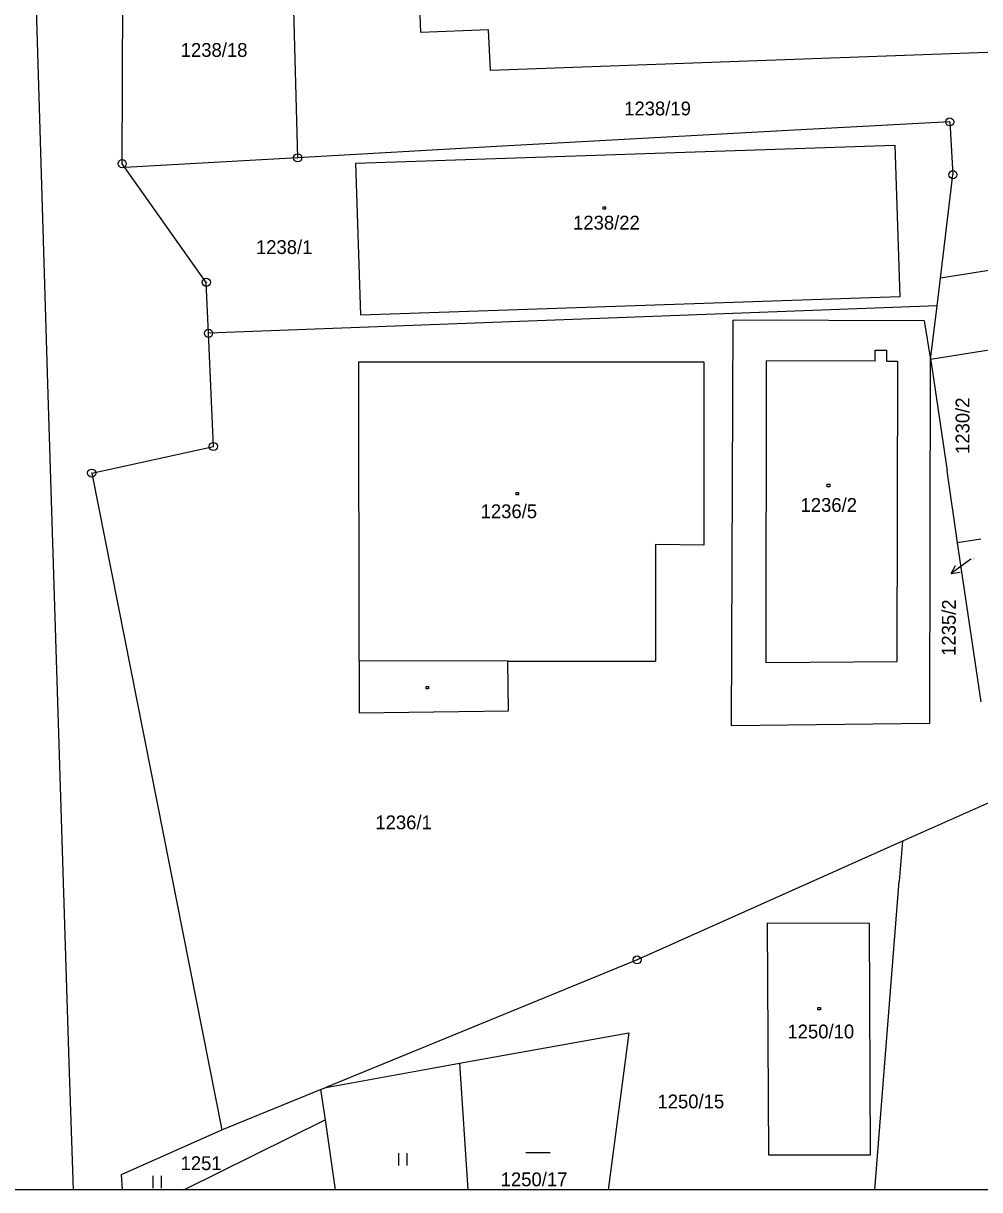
# Model space of a CAD drawing. Extents: x -468021 to -466942, y -1130484 to -1128584.
# Drawn here: x -467812 to -467694.3, y -1130484.4 to -1130340.9 of the extents above; entities that cross this region are included whole.
import ezdxf

# ---------------------------------------------------------------- set-up
doc = ezdxf.new("R2010")
doc.units = 0
doc.layers.add('Default', color=7, linetype='Continuous')
doc.layers.add('DKM', color=7, linetype='Continuous')

msp = doc.modelspace()

# ---------------------------------------------------------------- linework, layer by layer
at = {"layer": 'Default'}
msp.add_lwpolyline([(-468020.6, -1128583.91), (-466941.68, -1128583.91), (-466941.68, -1130484.41), (-468020.6, -1130484.41)], close=True, dxfattribs=at)
at = {"layer": 'DKM'}
for p, q in [((-467811.03, -1130318.68), (-467809, -1130385.26)), ((-467799.81, -1130358.16), (-467799.72, -1130327.35)), ((-467778.96, -1130329.97), (-467778.22, -1130357.43)), ((-467763.05, -1130342), (-467763.55, -1130329.32)), ((-467754.72, -1130341.69), (-467763.05, -1130342)), ((-467754.48, -1130346.7), (-467754.72, -1130341.69)), ((-467686.49, -1130344.23), (-467754.48, -1130346.7)), ((-467697.94, -1130353.01), (-467717.06, -1130354.05)), ((-467697.94, -1130353.01), (-467697.55, -1130359.51)), ((-467717.06, -1130354.05), (-467753.72, -1130356.05)), ((-467771.05, -1130358.1), (-467704.72, -1130355.86)), ((-467704.72, -1130355.86), (-467704.1, -1130374.55)), ((-467778.22, -1130357.43), (-467799.48, -1130358.62)), ((-467753.72, -1130356.05), (-467778.22, -1130357.43)), ((-467799.48, -1130358.62), (-467799.81, -1130358.16)), ((-467789.46, -1130372.76), (-467799.48, -1130358.62)), ((-467770.42, -1130376.78), (-467771.05, -1130358.1)), ((-467699.09, -1130372.25), (-467697.55, -1130359.51)), ((-467740.6, -1130363.46), (-467740.3, -1130363.46)), ((-467740.6, -1130363.76), (-467740.6, -1130363.46)), ((-467740.3, -1130363.76), (-467740.6, -1130363.76)), ((-467740.3, -1130363.46), (-467740.3, -1130363.76)), ((-467672.82, -1130368.13), (-467699.09, -1130372.25)), ((-467789.19, -1130379.03), (-467789.46, -1130372.76)), ((-467699.5, -1130375.66), (-467699.09, -1130372.25)), ((-467704.1, -1130374.55), (-467770.42, -1130376.78)), ((-467699.5, -1130375.66), (-467789.19, -1130379.03)), ((-467700.3, -1130382.24), (-467699.5, -1130375.66)), ((-467724.8, -1130427.31), (-467724.61, -1130377.39)), ((-467701.07, -1130377.48), (-467724.61, -1130377.39)), ((-467701.07, -1130377.48), (-467700.3, -1130382.24)), ((-467788.59, -1130392.96), (-467789.19, -1130379.03)), ((-467682.11, -1130379.37), (-467700.3, -1130382.24)), ((-467707.11, -1130382.44), (-467707.11, -1130381.11)), ((-467707.11, -1130381.11), (-467705.73, -1130381.11)), ((-467705.73, -1130381.11), (-467705.73, -1130382.45)), ((-467770.69, -1130382.53), (-467728.22, -1130382.52)), ((-467770.66, -1130419.35), (-467770.69, -1130382.53)), ((-467728.22, -1130382.52), (-467728.21, -1130405.08)), ((-467720.52, -1130419.59), (-467720.51, -1130382.42)), ((-467707.11, -1130382.44), (-467720.51, -1130382.42)), ((-467705.73, -1130382.45), (-467704.37, -1130382.45)), ((-467704.37, -1130382.45), (-467704.45, -1130419.44)), ((-467700.39, -1130427.04), (-467700.3, -1130382.24)), ((-467700.3, -1130382.24), (-467700.22, -1130382.67)), ((-467700.22, -1130382.67), (-467698.27, -1130395.95)), ((-467809, -1130385.26), (-467806.4, -1130468.75)), ((-467803.57, -1130396.23), (-467788.59, -1130392.96)), ((-467696.97, -1130404.81), (-467698.27, -1130395.95)), ((-467803.57, -1130396.23), (-467787.55, -1130477.06)), ((-467713.01, -1130397.6), (-467712.71, -1130397.6)), ((-467713.01, -1130397.9), (-467713.01, -1130397.6)), ((-467712.71, -1130397.6), (-467712.71, -1130397.9)), ((-467751.33, -1130398.62), (-467751.03, -1130398.62)), ((-467751.33, -1130398.92), (-467751.33, -1130398.62)), ((-467751.03, -1130398.92), (-467751.33, -1130398.92)), ((-467751.03, -1130398.62), (-467751.03, -1130398.92)), ((-467712.71, -1130397.9), (-467713.01, -1130397.9)), ((-467694.11, -1130404.36), (-467696.97, -1130404.81)), ((-467694.09, -1130424.37), (-467696.97, -1130404.81)), ((-467728.21, -1130405.08), (-467734.18, -1130405.01)), ((-467734.18, -1130405.01), (-467734.17, -1130419.36)), ((-467695.34, -1130406.84), (-467697.77, -1130408.6)), ((-467697.77, -1130408.6), (-467697.25, -1130407.61)), ((-467697.77, -1130408.6), (-467696.66, -1130408.42)), ((-467752.33, -1130419.36), (-467770.66, -1130419.35)), ((-467770.66, -1130419.35), (-467770.64, -1130425.74)), ((-467752.33, -1130419.36), (-467734.17, -1130419.36)), ((-467752.27, -1130425.47), (-467752.33, -1130419.36)), ((-467704.45, -1130419.44), (-467720.52, -1130419.59)), ((-467762.41, -1130422.47), (-467762.11, -1130422.47)), ((-467762.41, -1130422.77), (-467762.41, -1130422.47)), ((-467762.11, -1130422.77), (-467762.41, -1130422.77)), ((-467762.11, -1130422.47), (-467762.11, -1130422.77)), ((-467770.64, -1130425.74), (-467752.27, -1130425.47)), ((-467700.39, -1130427.04), (-467724.8, -1130427.31)), ((-467692.32, -1130436.42), (-467703.76, -1130441.53)), ((-467703.76, -1130441.53), (-467736.43, -1130456.13)), ((-467703.76, -1130441.53), (-467704.15, -1130446.43)), ((-467707.16, -1130484.41), (-467704.15, -1130446.43)), ((-467707.8, -1130451.64), (-467720.42, -1130451.61)), ((-467720.42, -1130451.61), (-467720.26, -1130480.11)), ((-467707.7, -1130480.11), (-467707.8, -1130451.64)), ((-467736.43, -1130456.13), (-467774.74, -1130471.82)), ((-467714.17, -1130461.99), (-467713.87, -1130461.99)), ((-467714.17, -1130462.29), (-467714.17, -1130461.99)), ((-467713.87, -1130461.99), (-467713.87, -1130462.29)), ((-467713.87, -1130462.29), (-467714.17, -1130462.29)), ((-467758.28, -1130468.86), (-467737.43, -1130465.1)), ((-467737.43, -1130465.1), (-467739.97, -1130484.41)), ((-467806.4, -1130468.75), (-467805.84, -1130484.41)), ((-467762.12, -1130469.55), (-467758.28, -1130468.86)), ((-467758.28, -1130468.86), (-467757.26, -1130484.41)), ((-467774.74, -1130471.82), (-467762.12, -1130469.55)), ((-467787.55, -1130477.06), (-467775.39, -1130472.09)), ((-467775.39, -1130472.09), (-467774.74, -1130471.82)), ((-467775.39, -1130472.09), (-467774.84, -1130475.83)), ((-467792.23, -1130484.41), (-467774.84, -1130475.83)), ((-467799.88, -1130482.52), (-467787.55, -1130477.06)), ((-467765.77, -1130481.43), (-467765.77, -1130479.93)), ((-467764.77, -1130479.93), (-467764.77, -1130481.43)), ((-467750.14, -1130479.83), (-467747.14, -1130479.83)), ((-467720.26, -1130480.11), (-467707.7, -1130480.11)), ((-467799.77, -1130484.41), (-467799.88, -1130482.52)), ((-467796.01, -1130484.21), (-467796.01, -1130482.71)), ((-467795.01, -1130482.71), (-467795.01, -1130484.21))]:
    msp.add_line(p, q, dxfattribs=at)
msp.add_lwpolyline([(-467774.84, -1130475.83), (-467773.58, -1130484.41)], dxfattribs=at)
for centre, radius in [((-467697.94, -1130353.01), 0.5), ((-467697.94, -1130353.01), 0.01), ((-467778.22, -1130357.43), 0.5), ((-467778.22, -1130357.43), 0.01), ((-467799.81, -1130358.16), 0.5), ((-467799.81, -1130358.16), 0.01), ((-467697.55, -1130359.51), 0.5), ((-467697.55, -1130359.51), 0.01), ((-467789.46, -1130372.76), 0.5), ((-467789.46, -1130372.76), 0.01), ((-467789.19, -1130379.03), 0.5), ((-467789.19, -1130379.03), 0.01), ((-467788.59, -1130392.96), 0.5), ((-467788.59, -1130392.96), 0.01), ((-467803.57, -1130396.23), 0.5), ((-467803.57, -1130396.23), 0.01), ((-467736.43, -1130456.13), 0.5), ((-467736.43, -1130456.13), 0.01)]:
    msp.add_circle(centre, radius, dxfattribs=at)

# ---------------------------------------------------------------- texts
for s, height, p in [('1238/18', 1.7, (-467792.61, -1130345.01)), ('1238/19', 1.7, (-467738.02, -1130352.21)), ('1238/22', 1.7, (-467744.31, -1130366.26)), ('1238/1', 1.7, (-467783.35, -1130369.27)), ('1236/5', 1.7, (-467755.69, -1130401.78)), ('1236/2', 1.7, (-467716.31, -1130401)), ('1235/2', 0.1, (-467695.34, -1130406.84)), ('1236/1', 1.7, (-467768.65, -1130440.06)), ('1250/10', 1.7, (-467717.92, -1130465.79)), ('1250/15', 1.7, (-467733.92, -1130474.4)), ('1251', 1.7, (-467792.63, -1130482)), ('1250/17', 1.7, (-467753.22, -1130483.99))]:
    msp.add_text(s, height=height, dxfattribs=at).set_placement(p)
for s, rotation, p in [('1230/2', 90, (-467695.52, -1130393.88)), ('1235/2', 89.6157, (-467697.23, -1130418.73))]:
    msp.add_text(s, height=1.7, rotation=rotation, dxfattribs=at).set_placement(p)

doc.saveas('drawing.dxf')
